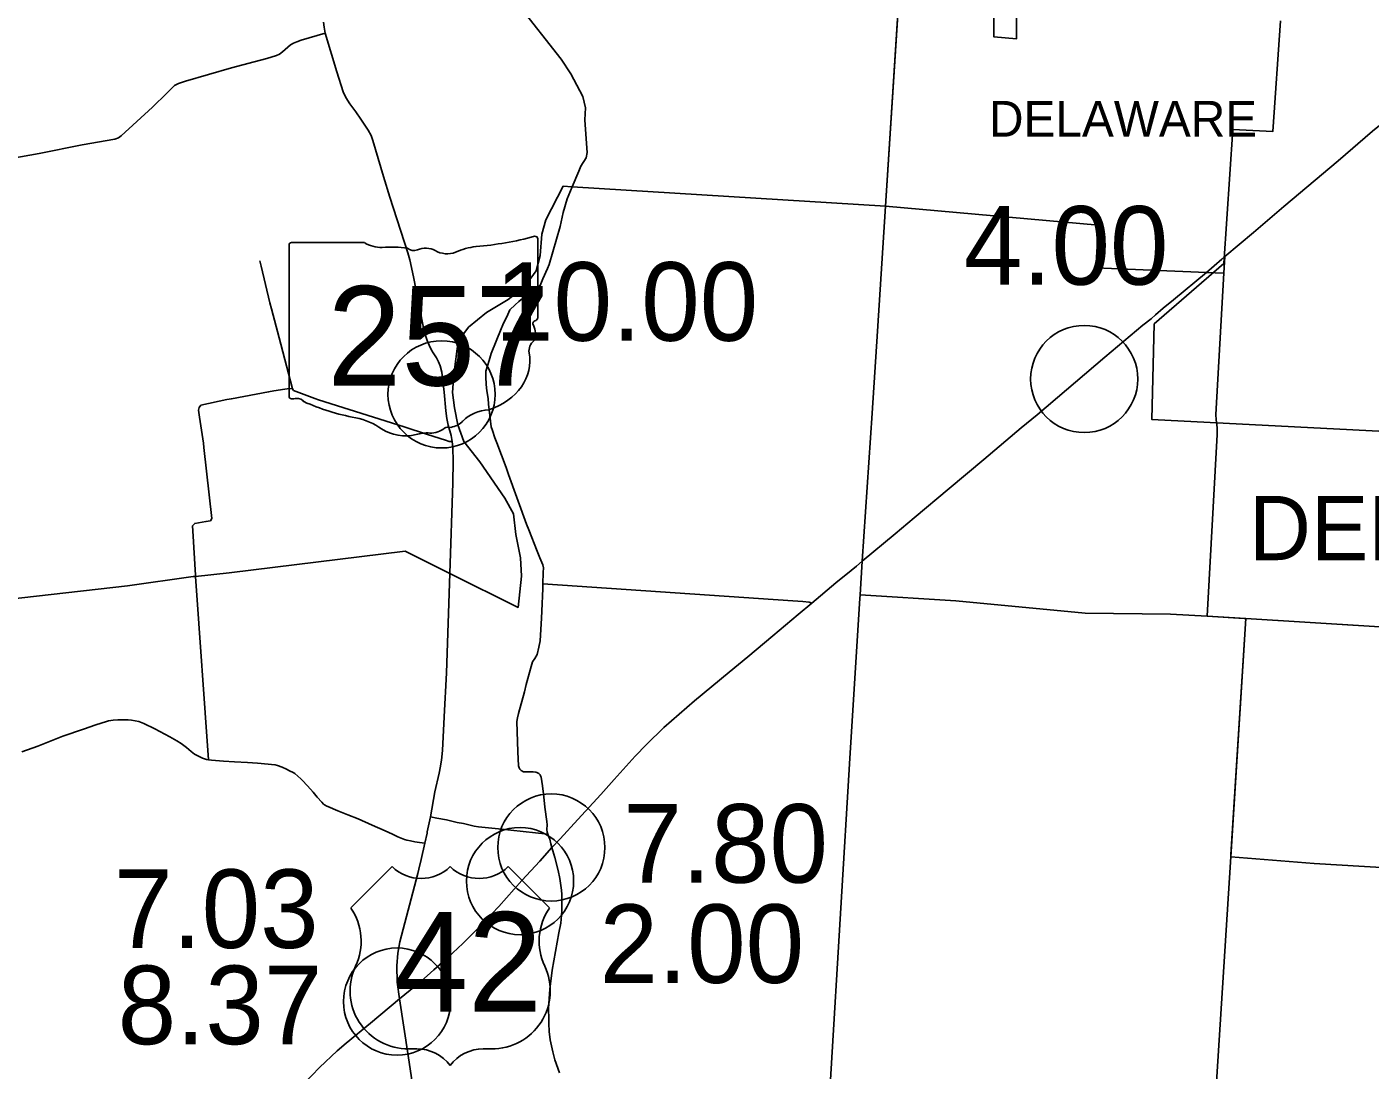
# Model space of a CAD drawing. Extents: x 1597222 to 1925846, y 496284 to 911751.
# Drawn here: x 1780898 to 1799698, y 815408 to 830013 of the extents above; entities that cross this region are included whole.
import ezdxf

# ---------------------------------------------------------------- set-up
doc = ezdxf.new("R2010")
doc.units = 0
for name, color, linetype in [('Default', 7, 'Continuous'), ('GM_X_City_Street', 7, 'Continuous'), ('GM_X_Corporation', 7, 'Continuous'), ('GM_X_Corporation_Text', 7, 'Continuous'), ('GM_X_County_Road', 7, 'Continuous'), ('GM_X_State_Route', 7, 'Continuous'), ('GM_X_State_Shield', 7, 'Continuous'), ('GM_X_Township', 7, 'Continuous'), ('GM_X_Township_Road', 7, 'Continuous'), ('GM_X_Township_Text', 7, 'Continuous'), ('GM_X_US_Route', 7, 'Continuous'), ('GM_X_US_Shield', 7, 'Continuous')]:
    doc.layers.add(name, color=color, linetype=linetype)

msp = doc.modelspace()

# ---------------------------------------------------------------- linework, layer by layer
at = {"layer": 'Default'}
for centre in [(1795696, 825083), (1786702, 824868), (1788238, 818525), (1787800, 818054), (1786079, 816368), (1786079, 816368)]:
    msp.add_circle(centre, 750, dxfattribs=at)
at = {"layer": 'GM_X_City_Street'}
msp.add_lwpolyline([(1797542, 824510), (1797538, 824584), (1797648, 826566), (1797666, 826798)], dxfattribs=at)
at = {"layer": 'GM_X_Corporation'}
for points in [[(1794748, 830490), (1794748, 829844), (1794432, 829873), (1794432, 830514)], [(1805265, 824074), (1796641, 824518), (1796676, 825855), (1797651, 826702), (1797775, 828578), (1798334, 828546), (1798442, 830097)]]:
    msp.add_lwpolyline(points, dxfattribs=at)
at = {"layer": 'GM_X_County_Road'}
for points in [[(1792915, 827504), (1793116, 830642)], [(1780019, 828053), (1781072, 828241), (1781672, 828363), (1782129, 828441), (1782181, 828458), (1782216, 828486), (1782656, 828889), (1782857, 829086), (1782966, 829190), (1783022, 829221), (1783116, 829251), (1783761, 829437), (1784081, 829523), (1784256, 829568), (1784391, 829611), (1784435, 829632), (1784475, 829661), (1784511, 829694), (1784590, 829760), (1784631, 829786), (1784675, 829805), (1784739, 829825), (1785075, 829924)], [(1792590, 822534), (1792728, 824607), (1792805, 825753), (1792915, 827502), (1792915, 827504)], [(1792558, 822011), (1792562, 822063), (1792590, 822534)], [(1791713, 807764), (1791713, 807764), (1791727, 808049), (1791747, 808435), (1791981, 812422), (1791996, 812680), (1792152, 815352), (1792421, 819851), (1792558, 822011)], [(1780828, 819865), (1781050, 819944), (1781402, 820082), (1781691, 820183), (1781861, 820241), (1782011, 820288), (1782042, 820296), (1782107, 820308), (1782172, 820313), (1782226, 820314), (1782272, 820313), (1782317, 820310), (1782363, 820305), (1782467, 820289), (1782536, 820259), (1782689, 820187), (1782899, 820076), (1782997, 820018), (1783056, 819981), (1783133, 819925), (1783197, 819870), (1783245, 819831), (1783272, 819816), (1783299, 819801), (1783327, 819788), (1783356, 819777), (1783385, 819767), (1783414, 819758), (1783439, 819754), (1783481, 819748), (1783650, 819735), (1783803, 819726), (1783988, 819713), (1784127, 819703), (1784372, 819682), (1784405, 819673), (1784469, 819651), (1784531, 819623), (1784574, 819600), (1784624, 819574), (1784647, 819559), (1784692, 819525), (1784732, 819486), (1784749, 819467), (1784825, 819388), (1784904, 819298), (1784959, 819231), (1785026, 819159), (1785050, 819133), (1785064, 819122), (1785094, 819104), (1785110, 819097), (1785248, 819040), (1785388, 818983), (1785533, 818924), (1785732, 818836), (1785914, 818757), (1786015, 818713), (1786091, 818676), (1786184, 818639), (1786216, 818628), (1786266, 818617), (1786329, 818603), (1786391, 818595), (1786468, 818586)], [(1786546, 818956), (1786635, 818936), (1786770, 818912), (1786920, 818877), (1787011, 818860), (1787156, 818825), (1787219, 818816), (1787498, 818787), (1787499, 818787)], [(1787499, 818787), (1788188, 818712), (1788200, 818681), (1788215, 818640), (1788230, 818576), (1788246, 818524)]]:
    msp.add_lwpolyline(points, dxfattribs=at)
at = {"layer": 'GM_X_State_Route'}
for points in [[(1785512, 828810), (1785504, 828821), (1785420, 828937), (1785361, 829025), (1785323, 829103), (1785237, 829384), (1785075, 829924), (1785057, 830010), (1785050, 830079)], [(1786687, 819666), (1786699, 819749), (1786713, 819884), (1786736, 820353), (1786769, 820971), (1786817, 822362), (1786859, 823630), (1786863, 823932), (1786858, 824119), (1786848, 824207), (1786835, 824290), (1786796, 824437), (1786775, 824531), (1786760, 824638), (1786736, 824900), (1786705, 825179), (1786684, 825266), (1786661, 825325), (1786630, 825381), (1786584, 825450), (1786562, 825489), (1786529, 825557), (1786500, 825620), (1786459, 825751), (1786384, 826129), (1786309, 826513), (1786256, 826749), (1786229, 826847), (1785980, 827630), (1785889, 827919), (1785741, 828423), (1785715, 828492), (1785677, 828567), (1785565, 828736), (1785512, 828810)], [(1786502, 818744), (1786546, 818956), (1786609, 819304), (1786669, 819567), (1786687, 819663), (1786687, 819666)], [(1786385, 818223), (1786418, 818357), (1786468, 818586), (1786499, 818725), (1786502, 818744)], [(1788344, 817330), (1788369, 817465), (1788384, 817635), (1788386, 817682), (1788383, 817868), (1788379, 817929), (1788358, 818089), (1788333, 818205), (1788285, 818386), (1788246, 818524)], [(1786113, 816405), (1786081, 816641), (1786075, 816867), (1786090, 817045), (1786116, 817206), (1786370, 818161), (1786385, 818223)], [(1788352, 815370), (1788288, 815554), (1788258, 815665), (1788224, 815834), (1788209, 815948), (1788201, 816063), (1788201, 816122), (1788200, 816272), (1788218, 816541), (1788249, 816808), (1788344, 817330)], [(1786361, 814768), (1786233, 815611), (1786113, 816405)]]:
    msp.add_lwpolyline(points, dxfattribs=at)
at = {"layer": 'GM_X_State_Shield'}
for p, q in [((1788048, 825939), (1788048, 827045)), ((1788048, 825939), (1788048, 827045)), ((1784567, 826956), (1784567, 824843)), ((1784567, 826956), (1784567, 824843)), ((1785621, 826993), (1784602, 826993)), ((1785621, 826993), (1784602, 826993)), ((1788047, 825940), (1788048, 825939)), ((1788047, 825940), (1788048, 825939))]:
    msp.add_line(p, q, dxfattribs=at)
for centre, major_axis, start_param, end_param in [((1786808, 829874), (3691, 0), 4.814394, 5.042369), ((1786808, 829874), (3691, 0), 4.814394, 5.042369), ((1788009, 827050), (38.7, 0), 6.141152, 7.989035), ((1788009, 827050), (38.7, 0), 6.141152, 7.989035), ((1784607, 826961), (40.3, 0), 1.712693, 3.28349), ((1784607, 826961), (40.3, 0), 1.712693, 3.28349), ((1785864, 827238), (391, 0), 4.042523, 4.731795), ((1785864, 827238), (391, 0), 4.042523, 4.731795), ((1785993, 825806), (1404, 0), 1.404758, 1.657858), ((1785993, 825806), (1404, 0), 1.404758, 1.657858), ((1786312, 826972), (113, 0), 3.836095, 5.185415), ((1786312, 826972), (113, 0), 3.836095, 5.185415), ((1786478, 826727), (235, 0), 0.950623, 2.079405), ((1786478, 826727), (235, 0), 0.950623, 2.079405), ((1786780, 827062), (282, 0), 4.081561, 5.145723), ((1786780, 827062), (282, 0), 4.081561, 5.145723), ((1787279, 826347), (743, 0), 1.699011, 2.107814), ((1787279, 826347), (743, 0), 1.699011, 2.107814), ((1788039, 825858), (60, 0), 1.883978, 3.671073), ((1788039, 825858), (60, 0), 1.883978, 3.671073), ((1788006, 825935), (41.5, 0), 5.05454, 6.418171), ((1788006, 825935), (41.5, 0), 5.05454, 6.418171), ((1787657, 825719), (360, 0), 5.934695, 6.695948), ((1787657, 825719), (360, 0), 5.934695, 6.695948), ((1788187, 825477), (262, 0), 2.387724, 3.262537), ((1788187, 825477), (262, 0), 2.387724, 3.262537), ((1787015, 825336), (923, 0), 5.101752, 6.440018), ((1787015, 825336), (923, 0), 5.101752, 6.440018), ((1784608, 824838), (40.7, 0), 3.00124, 4.508301), ((1784608, 824838), (40.7, 0), 3.00124, 4.508301), ((1784614, 825055), (310, 0), 4.665946, 4.897461), ((1784614, 825055), (310, 0), 4.665946, 4.897461), ((1784677, 824721), (112, 0), 0.519207, 1.627899), ((1784677, 824721), (112, 0), 0.519207, 1.627899), ((1786091, 826620), (2665, 0), 4.195997, 4.488961), ((1786091, 826620), (2665, 0), 4.195997, 4.488961), ((1787404, 824250), (506, 0), 1.647645, 2.488434), ((1787404, 824250), (506, 0), 1.647645, 2.488434), ((1785296, 823894), (834, 0), 0.823519, 1.323587), ((1785296, 823894), (834, 0), 0.823519, 1.323587), ((1786198, 824711), (529, 0), 4.026481, 4.996735), ((1786198, 824711), (529, 0), 4.026481, 4.996735), ((1786542, 824552), (282, 0), 4.691044, 5.507374), ((1786542, 824552), (282, 0), 4.691044, 5.507374), ((1786797, 824348), (79.4, 0), 1.147584, 2.315152), ((1786797, 824348), (79.4, 0), 1.147584, 2.315152), ((1786763, 824638), (298, 0), 4.937069, 5.64225), ((1786763, 824638), (298, 0), 4.937069, 5.64225), ((1786504, 823980), (435, 0), 1.495662, 1.94098), ((1786504, 823980), (435, 0), 1.495662, 1.94098)]:
    msp.add_ellipse(centre, major_axis=major_axis, ratio=0.8, start_param=start_param, end_param=end_param, dxfattribs=at)
at = {"layer": 'GM_X_Township'}
for points in [[(1792915, 827502), (1793120, 830695), (1793232, 832236), (1793303, 833333), (1793352, 834099), (1793647, 838152), (1793839, 840685)], [(1779756, 821898), (1782305, 822188), (1783225, 822317), (1783260, 822320), (1783730, 822371), (1786192, 822674), (1786817, 822362), (1787772, 821886), (1787820, 822322), (1787807, 822581), (1787740, 822908), (1787709, 823197), (1787588, 823413), (1787237, 823925), (1787015, 824208), (1786931, 824440), (1786884, 824679), (1786853, 824895), (1786873, 825147), (1786934, 825612), (1787079, 825811), (1787332, 826016), (1787635, 826195), (1787864, 826374), (1788025, 826596), (1788083, 826812), (1788106, 827111), (1788160, 827310), (1788402, 827781), (1788529, 827772), (1792915, 827502), (1795894, 827235), (1795858, 826641), (1797406, 826576), (1797648, 826566), (1797538, 824584), (1797542, 824510), (1797556, 824405), (1797555, 824304), (1797417, 821763), (1797959, 821729), (1797746, 818394), (1797534, 815021)], [(1797959, 821729), (1805087, 821285), (1806012, 821223), (1808814, 821113), (1810371, 821059), (1811439, 820998), (1811977, 820984), (1816437, 820719), (1817422, 820661), (1819403, 820562)]]:
    msp.add_lwpolyline(points, dxfattribs=at)
at = {"layer": 'GM_X_Township_Road'}
for points in [[(1788621, 827994), (1788650, 828063), (1788726, 828178), (1788739, 828252), (1788721, 828512), (1788707, 828711), (1788718, 828879), (1788680, 829037), (1788510, 829354), (1788376, 829562), (1787776, 830325), (1787442, 830711), (1787118, 831016), (1786817, 831334), (1786550, 831763), (1786230, 832458), (1785968, 832975), (1785767, 833439), (1785710, 833597), (1785701, 833646), (1785722, 834226), (1785735, 834569), (1785736, 834651), (1785723, 834708)], [(1788120, 822216), (1788120, 822216), (1788126, 822374), (1788128, 822441), (1788118, 822483), (1788077, 822580), (1788038, 822675), (1787922, 822970), (1787889, 823052), (1787640, 823748), (1787607, 823843), (1787475, 824188), (1787448, 824260), (1787416, 824361), (1787398, 824415), (1787361, 824729), (1787352, 824812), (1787337, 824916), (1787324, 825006), (1787323, 825112), (1787322, 825191), (1787368, 825343), (1787398, 825442), (1787537, 825784), (1787560, 825841), (1787628, 825984), (1787658, 826050), (1787734, 826123), (1787781, 826168), (1787903, 826268), (1787957, 826313), (1788002, 826340), (1788083, 826391), (1788119, 826483), (1788184, 826628), (1788209, 826684), (1788361, 827216), (1788405, 827412), (1788461, 827606), (1788529, 827772), (1788621, 827994)], [(1784618, 824946), (1784452, 825573), (1784431, 825658), (1784320, 826065), (1784297, 826149), (1784176, 826663), (1784159, 826737)], [(1783259, 822338), (1783221, 822958), (1783217, 823026), (1783247, 823062), (1783403, 823087), (1783468, 823098), (1783486, 823128), (1783376, 824125), (1783369, 824183), (1783314, 824549), (1783299, 824645), (1783309, 824683), (1783335, 824717), (1783697, 824794), (1783760, 824807), (1784280, 824902), (1784353, 824916), (1784510, 824941), (1784574, 824952), (1784618, 824946), (1784632, 824924), (1784929, 824812), (1784979, 824793), (1786179, 824415), (1786504, 824307), (1786757, 824225), (1786806, 824209), (1786824, 824206), (1786848, 824207)], [(1797542, 824510), (1797556, 824405), (1797555, 824304), (1797417, 821763)], [(1783439, 819754), (1783260, 822320), (1783259, 822338)], [(1788188, 818712), (1788180, 818740), (1788177, 818778), (1788179, 818842), (1788175, 818887), (1788149, 819089), (1788131, 819232), (1788115, 819387), (1788096, 819509), (1788093, 819519), (1788088, 819530), (1788082, 819541), (1788074, 819550), (1788065, 819559), (1788056, 819566), (1788045, 819572), (1788034, 819576), (1788022, 819579), (1787982, 819582), (1787863, 819584), (1787850, 819586), (1787838, 819590), (1787827, 819596), (1787817, 819603), (1787807, 819611), (1787799, 819620), (1787791, 819631), (1787786, 819642), (1787781, 819654), (1787778, 819666), (1787768, 819865), (1787757, 820287), (1787767, 820339), (1787779, 820400), (1787861, 820706), (1787888, 820806), (1787956, 821060), (1787974, 821125), (1788006, 821169), (1788040, 821227), (1788064, 821330), (1788084, 821417), (1788101, 821734), (1788106, 821833), (1788117, 822149), (1788120, 822216)], [(1788120, 822216), (1791616, 821980), (1791759, 821967), (1791848, 821957), (1791884, 821945)], [(1792562, 822063), (1793900, 821979), (1795708, 821807), (1796906, 821790), (1797417, 821763)], [(1797417, 821763), (1797934, 821731)], [(1797959, 821729), (1797748, 818428)], [(1797934, 821731), (1797959, 821729), (1805080, 821285)], [(1797748, 818428), (1797746, 818394), (1798913, 818302), (1802044, 818116), (1802541, 818082), (1802940, 818062), (1804889, 817941), (1805812, 817899)]]:
    msp.add_lwpolyline(points, dxfattribs=at)
at = {"layer": 'GM_X_US_Route'}
for points in [[(1797621, 826760), (1797666, 826798), (1798064, 827135), (1798491, 827497), (1799248, 828136), (1799732, 828551), (1800024, 828792), (1800425, 829142)], [(1796695, 825983), (1796802, 826075), (1796947, 826193), (1797406, 826576), (1797621, 826760)], [(1792508, 822464), (1792590, 822534), (1793050, 822917), (1793314, 823141), (1793805, 823550), (1794289, 823956), (1794815, 824398), (1795038, 824581), (1795987, 825387), (1796517, 825835), (1796631, 825927), (1796695, 825983)], [(1784670, 815110), (1784992, 815444), (1785243, 815676), (1785368, 815784), (1785705, 816066), (1786113, 816405), (1786413, 816648), (1786595, 816812), (1786790, 816985), (1786998, 817182), (1787210, 817389), (1787502, 817701), (1787826, 818063), (1788077, 818333), (1788246, 818524), (1788360, 818647), (1788609, 818917), (1788930, 819268), (1789118, 819475), (1789413, 819805), (1789572, 819966), (1789812, 820205), (1790241, 820577), (1790726, 820980), (1790989, 821194), (1791340, 821489), (1791695, 821786), (1791884, 821945), (1792222, 822228), (1792434, 822401), (1792508, 822464)]]:
    msp.add_lwpolyline(points, dxfattribs=at)
at = {"layer": 'GM_X_US_Shield'}
for p, q in [((1786010, 818258), (1785430, 817678)), ((1786010, 818258), (1785430, 817678)), ((1788214, 817678), (1787634, 818258)), ((1788214, 817678), (1787634, 818258)), ((1786242, 815706), (1786358, 815706)), ((1786242, 815706), (1786358, 815706)), ((1787286, 815706), (1787402, 815706)), ((1787286, 815706), (1787402, 815706))]:
    msp.add_line(p, q, dxfattribs=at)
for centre, radius, start, end in [((1786416, 818672), 580, 225.573, 314.427), ((1786416, 818672), 580, 225.573, 314.427), ((1787228, 818672), 580, 225.573, 314.427), ((1787228, 818672), 580, 225.573, 314.427), ((1784765, 817212), 812, 334.5471, 35.0009), ((1784765, 817212), 812, 334.5471, 35.0009), ((1788879, 817212), 812, 144.9991, 205.4529), ((1788879, 817212), 812, 144.9991, 205.4529), ((1786233, 816518), 812, 154.8319, 270.6383), ((1786233, 816518), 812, 154.8319, 270.6383), ((1787411, 816518), 812, 269.3617, 25.1681), ((1787411, 816518), 812, 269.3617, 25.1681), ((1786358, 815126), 580, 36.8699, 90), ((1786358, 815126), 580, 36.8699, 90), ((1787286, 815126), 580, 90, 143.1301), ((1787286, 815126), 580, 90, 143.1301)]:
    msp.add_arc(centre, radius, start, end, dxfattribs=at)

# ---------------------------------------------------------------- texts
at = {"layer": 'Default'}
for s, p in [('4.00', (1794012, 826403)), ('10.00', (1787452, 825618)), ('7.80', (1789247, 818032)), ('7.03', (1782118, 817118)), ('2.00', (1788913, 816629)), ('8.37', (1782169, 815771))]:
    msp.add_text(s, height=1100, dxfattribs=at).set_placement(p)
at = {"layer": 'GM_X_Corporation_Text'}
msp.add_text('DELAWARE', height=500, rotation=0, dxfattribs=at).set_placement((1794364, 828476))
at = {"layer": 'GM_X_State_Shield'}
msp.add_text('257', height=1392.2, dxfattribs=at).set_placement((1785103, 824992))
msp.add_text('257', height=1392.2, dxfattribs=at).set_placement((1785103, 824992))
at = {"layer": 'GM_X_Township_Text'}
msp.add_text('DELAWARE', height=900, rotation=0, dxfattribs=at).set_placement((1798000, 822547))
at = {"layer": 'GM_X_US_Shield'}
msp.add_text('42', height=1392.2, dxfattribs=at).set_placement((1786038, 816228))
msp.add_text('42', height=1392.2, dxfattribs=at).set_placement((1786038, 816228))

doc.saveas('drawing.dxf')
